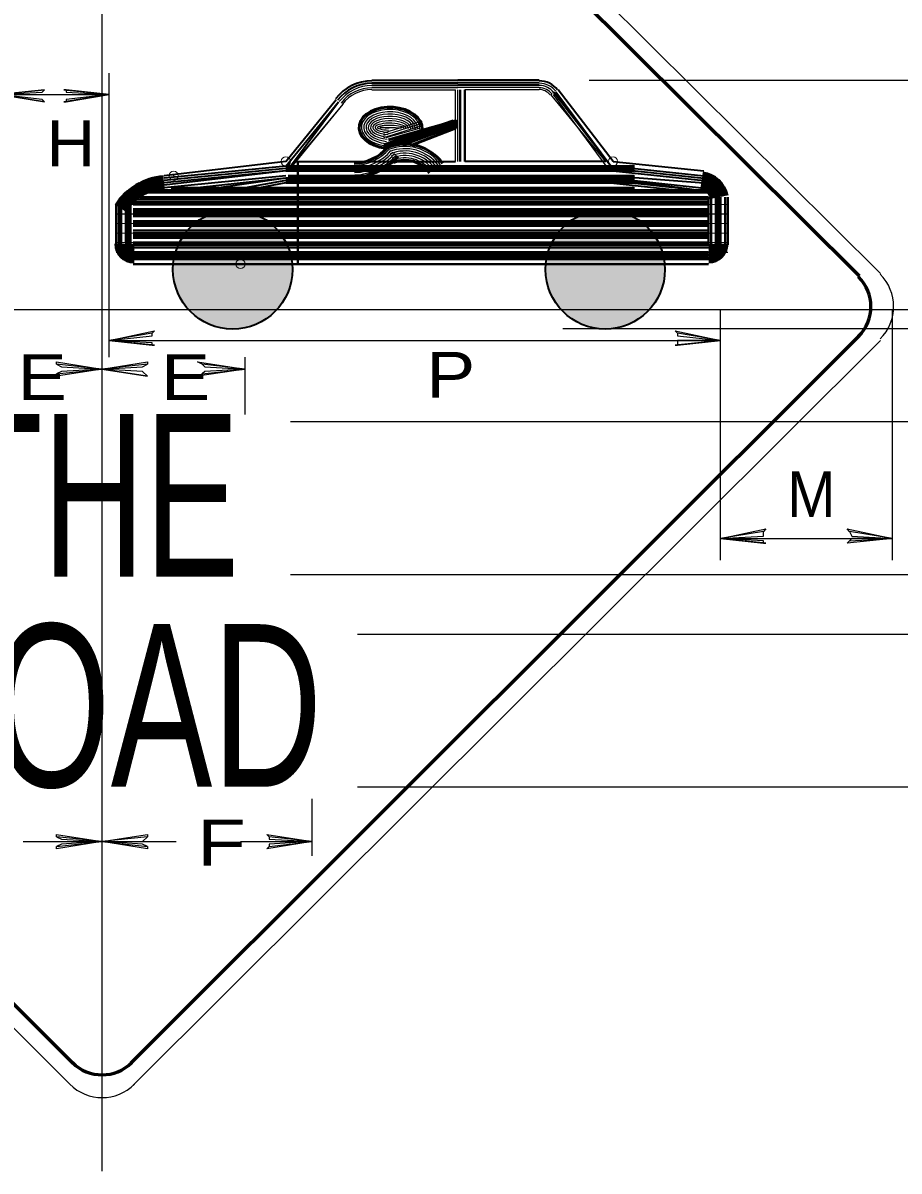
# Model space of a CAD drawing. Extents: x -0.018 to 0.195, y -0.006 to 0.263.
# Drawn here: x 0.0839 to 0.1297, y 0.1052 to 0.1654 of the extents above; entities that cross this region are included whole.
import ezdxf
from ezdxf.enums import TextEntityAlignment as Align

# ---------------------------------------------------------------- set-up
doc = ezdxf.new("R2010")
doc.units = 0
doc.header["$LTSCALE"] = 0.00096
doc.header["$PDMODE"] = 32
doc.header["$PDSIZE"] = 0.00048
doc.linetypes.add('DOT_DASHED', pattern=[7.7, 5, -1.2, 0.3, -1.2])
doc.layers.add('1', color=7, linetype='Continuous', lineweight=25)
doc.layers.add('12', color=7, linetype='Continuous', lineweight=13)

msp = doc.modelspace()

# ---------------------------------------------------------------- hatches: boundary and pattern name
at = {"layer": '12'}
for points in [[(0.097966, 0.152467, 1), (0.091717, 0.152467, 1)], [(0.117463, 0.152467, 1), (0.111214, 0.152467, 1)]]:
    msp.add_hatch(color=256, dxfattribs=at).paths.add_polyline_path(points)

# ---------------------------------------------------------------- linework, layer by layer
at = {"layer": '1', "linetype": 'DOT_DASHED'}
for p, q in [((0.088, 0.20175), (0.088, 0.10525)), ((0.032375, 0.150375), (0.143125, 0.150375))]:
    msp.add_line(p, q, dxfattribs=at)
at = {"layer": '1'}
for p, q in [((0.1135, 0.162375), (0.1335, 0.162375)), ((0.129375, 0.13725), (0.129375, 0.150375)), ((0.112125, 0.149375), (0.154625, 0.149375)), ((0.097875, 0.1445), (0.143, 0.1445)), ((0.120375, 0.138375), (0.129375, 0.138375)), ((0.097875, 0.1365), (0.143, 0.1365)), ((0.101375, 0.133375), (0.143, 0.133375)), ((0.101375, 0.125375), (0.143, 0.125375))]:
    msp.add_line(p, q, dxfattribs=at)
msp.add_lwpolyline([(0.127125, 0.13875), (0.12725, 0.1385), (0.129375, 0.138375), (0.127125, 0.13875), (0.127, 0.138875), (0.129375, 0.138375), (0.12725, 0.138375), (0.127125, 0.13825), (0.129375, 0.138375), (0.127, 0.138125), (0.127125, 0.13825)], dxfattribs=at)
at = {"layer": '12', "lineweight": 25}
for p, q in [((0.089625, 0.191125), (0.12875, 0.15225)), ((0.088375, 0.147875), (0.088375, 0.16275)), ((0.102125, 0.162), (0.106625, 0.162)), ((0.102125, 0.161875), (0.1065, 0.161875)), ((0.1065, 0.158125), (0.1065, 0.161875)), ((0.110875, 0.162), (0.106625, 0.162)), ((0.106625, 0.158125), (0.106625, 0.161875)), ((0.110875, 0.161875), (0.107, 0.161875)), ((0.082625, 0.161625), (0.088375, 0.161625)), ((0.114375, 0.158125), (0.1115, 0.161625)), ((0.1145, 0.15775), (0.111625, 0.161625)), ((0.097875, 0.15775), (0.100625, 0.161125)), ((0.097875, 0.15775), (0.100625, 0.161125)), ((0.098125, 0.158125), (0.100625, 0.161125)), ((0.10275, 0.159625), (0.10475, 0.16025)), ((0.10275, 0.1595), (0.10475, 0.160125)), ((0.10275, 0.159375), (0.10475, 0.16)), ((0.102875, 0.159375), (0.104625, 0.159875)), ((0.08875, 0.155375), (0.12075, 0.155375)), ((0.08875, 0.153375), (0.12075, 0.153375)), ((0.120375, 0.13725), (0.120375, 0.150375)), ((0.086375, 0.10975), (0.04725, 0.14875)), ((0.088375, 0.14875), (0.120375, 0.14875)), ((0.12875, 0.14875), (0.089625, 0.10975)), ((0.0955, 0.144875), (0.0955, 0.147875)), ((0.099, 0.12175), (0.099, 0.12475)), ((0.09525, 0.1225), (0.099, 0.1225))]:
    msp.add_line(p, q, dxfattribs=at)
at = {"layer": '12', "lineweight": 60}
for p, q in [((0.0895, 0.190125), (0.127625, 0.152125)), ((0.0865, 0.110875), (0.048375, 0.149)), ((0.127625, 0.149), (0.0895, 0.110875))]:
    msp.add_line(p, q, dxfattribs=at)
at = {"layer": '12', "lineweight": 35}
for p, q in [((0.102125, 0.162375), (0.106625, 0.162375)), ((0.110875, 0.162375), (0.106625, 0.162375)), ((0.102125, 0.16225), (0.106625, 0.16225)), ((0.102125, 0.162125), (0.106625, 0.162125)), ((0.110875, 0.16225), (0.106625, 0.16225)), ((0.110875, 0.162125), (0.106625, 0.162125)), ((0.114625, 0.157875), (0.111625, 0.16175)), ((0.114625, 0.157875), (0.11175, 0.16175)), ((0.11475, 0.158125), (0.111875, 0.161875)), ((0.097625, 0.158125), (0.10025, 0.161375)), ((0.097625, 0.157875), (0.100375, 0.16125)), ((0.097875, 0.157875), (0.100375, 0.16125)), ((0.097625, 0.158125), (0.09125, 0.157375)), ((0.097625, 0.157875), (0.09125, 0.15725)), ((0.097625, 0.15775), (0.09125, 0.157125)), ((0.097625, 0.157625), (0.09125, 0.157)), ((0.097625, 0.157625), (0.09125, 0.156875)), ((0.098125, 0.158125), (0.1065, 0.158125)), ((0.114375, 0.158125), (0.107, 0.158125)), ((0.11475, 0.158125), (0.1195, 0.157625)), ((0.11475, 0.157875), (0.1195, 0.157375)), ((0.11475, 0.15775), (0.1195, 0.15725)), ((0.11475, 0.157625), (0.1195, 0.157125)), ((0.11475, 0.157625), (0.1195, 0.157125)), ((0.097625, 0.157375), (0.09125, 0.15675)), ((0.097625, 0.15725), (0.093, 0.15675)), ((0.097625, 0.15725), (0.094125, 0.15675)), ((0.097625, 0.157125), (0.0955, 0.15675)), ((0.097625, 0.157), (0.09625, 0.15675)), ((0.114625, 0.15725), (0.11925, 0.156625)), ((0.114625, 0.157125), (0.11925, 0.156625)), ((0.114625, 0.157), (0.11925, 0.1565)), ((0.11475, 0.157375), (0.1195, 0.157)), ((0.11475, 0.15725), (0.119375, 0.15675))]:
    msp.add_line(p, q, dxfattribs=at)
at = {"layer": '12', "lineweight": 40}
for p, q in [((0.10675, 0.158125), (0.10675, 0.161875)), ((0.10675, 0.158125), (0.10675, 0.161875)), ((0.107, 0.158125), (0.107, 0.161875)), ((0.097625, 0.157875), (0.115875, 0.157875)), ((0.097625, 0.15775), (0.115875, 0.15775)), ((0.097625, 0.157625), (0.115875, 0.157625)), ((0.097625, 0.157625), (0.115875, 0.157625)), ((0.09825, 0.15275), (0.09825, 0.158125)), ((0.097625, 0.15725), (0.115875, 0.15725)), ((0.097625, 0.157125), (0.115875, 0.157125)), ((0.097625, 0.157125), (0.115875, 0.157125)), ((0.097625, 0.157), (0.115875, 0.157)), ((0.09775, 0.157375), (0.115875, 0.157375)), ((0.090125, 0.1565), (0.11975, 0.1565)), ((0.0905, 0.156625), (0.11975, 0.156625)), ((0.090875, 0.156625), (0.11975, 0.156625)), ((0.091625, 0.15675), (0.115875, 0.15675)), ((0.08875, 0.15375), (0.08875, 0.155875)), ((0.088875, 0.15375), (0.088875, 0.155875)), ((0.089, 0.15375), (0.089, 0.155875)), ((0.089, 0.15375), (0.089, 0.155875)), ((0.08925, 0.15375), (0.08925, 0.155875)), ((0.089375, 0.15375), (0.089375, 0.155875)), ((0.0895, 0.15375), (0.0895, 0.155875)), ((0.0895, 0.15375), (0.0895, 0.155875)), ((0.089625, 0.156125), (0.11975, 0.156125)), ((0.089625, 0.156125), (0.11975, 0.156125)), ((0.089625, 0.156), (0.11975, 0.156)), ((0.089625, 0.155875), (0.11975, 0.155875)), ((0.09, 0.15625), (0.11975, 0.15625)), ((0.11975, 0.15625), (0.11975, 0.15375)), ((0.119875, 0.15625), (0.119875, 0.15375)), ((0.119875, 0.15625), (0.119875, 0.15375)), ((0.120125, 0.15625), (0.120125, 0.15375)), ((0.12025, 0.15625), (0.12025, 0.15375)), ((0.120375, 0.15625), (0.120375, 0.15375)), ((0.120375, 0.15625), (0.120375, 0.15375)), ((0.120625, 0.15625), (0.120625, 0.15375)), ((0.12075, 0.15625), (0.12075, 0.15375)), ((0.089625, 0.155625), (0.11975, 0.155625)), ((0.089625, 0.155625), (0.11975, 0.155625)), ((0.089625, 0.1555), (0.11975, 0.1555)), ((0.089625, 0.155375), (0.11975, 0.155375)), ((0.089625, 0.15525), (0.11975, 0.15525)), ((0.089625, 0.15525), (0.11975, 0.15525)), ((0.089625, 0.155), (0.11975, 0.155)), ((0.089625, 0.154875), (0.11975, 0.154875)), ((0.089625, 0.15475), (0.11975, 0.15475)), ((0.089625, 0.15475), (0.11975, 0.15475)), ((0.089625, 0.1545), (0.11975, 0.1545)), ((0.089625, 0.154375), (0.11975, 0.154375)), ((0.089625, 0.15425), (0.11975, 0.15425)), ((0.089625, 0.15425), (0.11975, 0.15425)), ((0.089625, 0.154125), (0.11975, 0.154125)), ((0.089625, 0.153875), (0.11975, 0.153875)), ((0.089625, 0.15375), (0.11975, 0.15375)), ((0.089625, 0.15375), (0.11975, 0.15375)), ((0.089625, 0.153625), (0.11975, 0.153625)), ((0.089625, 0.153375), (0.11975, 0.153375)), ((0.089625, 0.15325), (0.11975, 0.15325)), ((0.089625, 0.15325), (0.11975, 0.15325)), ((0.089625, 0.153125), (0.11975, 0.153125)), ((0.089625, 0.153), (0.11975, 0.153)), ((0.089625, 0.15275), (0.11975, 0.15275))]:
    msp.add_line(p, q, dxfattribs=at)
at = {"layer": '12', "lineweight": 53}
for p, q in [((0.106625, 0.16025), (0.10275, 0.158875)), ((0.106375, 0.16025), (0.10275, 0.159)), ((0.1065, 0.160125), (0.1035, 0.159)), ((0.1065, 0.16), (0.10375, 0.159))]:
    msp.add_line(p, q, dxfattribs=at)
at = {"layer": '12'}
for p, q in [((0.08875, 0.155875), (0.12075, 0.155875)), ((0.08875, 0.154875), (0.12075, 0.154875)), ((0.08875, 0.154375), (0.12075, 0.154375)), ((0.08875, 0.153875), (0.12075, 0.153875)), ((0.089875, 0.15275), (0.1195, 0.15275))]:
    msp.add_line(p, q, dxfattribs=at)
at = {"layer": '12', "lineweight": 25}
for points in [[(0.085, 0.16125), (0.084875, 0.161375), (0.082625, 0.161625), (0.085, 0.16125), (0.085, 0.16125), (0.082625, 0.161625), (0.084875, 0.16175), (0.085, 0.161875), (0.082625, 0.161625), (0.085, 0.161875), (0.085, 0.161875)], [(0.086125, 0.161875), (0.086125, 0.16175), (0.088375, 0.161625), (0.086125, 0.161875), (0.086, 0.161875), (0.088375, 0.161625), (0.086125, 0.161375), (0.086125, 0.16125), (0.088375, 0.161625), (0.086, 0.16125), (0.086125, 0.16125)], [(0.090625, 0.1485), (0.090625, 0.148625), (0.088375, 0.14875), (0.090625, 0.1485), (0.09075, 0.1485), (0.088375, 0.14875), (0.090625, 0.149), (0.090625, 0.149125), (0.088375, 0.14875), (0.09075, 0.14925), (0.090625, 0.149125)], [(0.118125, 0.149125), (0.118125, 0.149), (0.120375, 0.14875), (0.118125, 0.149125), (0.118, 0.14925), (0.120375, 0.14875), (0.118125, 0.14875), (0.118125, 0.1485), (0.120375, 0.14875), (0.118, 0.1485), (0.118125, 0.1485)], [(0.085625, 0.1475), (0.085875, 0.147375), (0.088, 0.14725), (0.085625, 0.1475), (0.085625, 0.147625), (0.088, 0.14725), (0.085875, 0.147125), (0.085625, 0.147), (0.088, 0.14725), (0.085625, 0.146875), (0.085625, 0.147)], [(0.090375, 0.146875), (0.090125, 0.147125), (0.088, 0.14725), (0.090375, 0.146875), (0.090375, 0.146875), (0.088, 0.14725), (0.090125, 0.147375), (0.090375, 0.1475), (0.088, 0.14725), (0.090375, 0.147625), (0.090375, 0.1475)], [(0.09325, 0.1475), (0.093375, 0.147375), (0.0955, 0.14725), (0.09325, 0.1475), (0.093, 0.147625), (0.0955, 0.14725), (0.093375, 0.147125), (0.09325, 0.147), (0.0955, 0.14725), (0.093, 0.146875), (0.09325, 0.147)], [(0.122625, 0.138125), (0.122625, 0.13825), (0.120375, 0.138375), (0.122625, 0.138125), (0.12275, 0.138125), (0.120375, 0.138375), (0.122625, 0.1385), (0.122625, 0.13875), (0.120375, 0.138375), (0.12275, 0.138875), (0.122625, 0.13875)], [(0.085625, 0.12275), (0.085875, 0.122625), (0.088, 0.1225), (0.085625, 0.12275), (0.085625, 0.122875), (0.088, 0.1225), (0.085875, 0.122375), (0.085625, 0.12225), (0.088, 0.1225), (0.085625, 0.122125), (0.085625, 0.12225)], [(0.090375, 0.12225), (0.090125, 0.122375), (0.088, 0.1225), (0.090375, 0.12225), (0.090375, 0.122125), (0.088, 0.1225), (0.090125, 0.1225), (0.090375, 0.12275), (0.088, 0.1225), (0.090375, 0.122875), (0.090375, 0.12275)], [(0.09675, 0.12275), (0.09675, 0.122625), (0.099, 0.1225), (0.09675, 0.12275), (0.096625, 0.122875), (0.099, 0.1225), (0.09675, 0.122375), (0.09675, 0.12225), (0.099, 0.1225), (0.096625, 0.122125), (0.09675, 0.12225)], [(0.083875, 0.1225), (0.088, 0.1225), (0.091875, 0.1225)]]:
    msp.add_lwpolyline(points, dxfattribs=at)
at = {"layer": '12', "lineweight": 53}
msp.add_lwpolyline([(0.103, 0.15925), (0.1065, 0.16025), (0.1065, 0.159875), (0.10425, 0.159)], dxfattribs=at)
at = {"layer": '12', "lineweight": 35}
for centre in [(0.094842, 0.152467), (0.114339, 0.152467)]:
    msp.add_circle(centre, 0.003125, dxfattribs=at)
for centre, radius, start, end in [((0.102131, 0.159941), 0.0024, 90, 142.46745), ((0.102131, 0.159941), 0.00228, 90, 142.46745), ((0.11089, 0.161141), 0.0012, 37.53138, 90)]:
    msp.add_arc(centre, radius, start, end, dxfattribs=at)
at = {"layer": '12', "lineweight": 25}
for centre, radius, start, end in [((0.102131, 0.159941), 0.00216, 90, 142.46745), ((0.102131, 0.159941), 0.00204, 90, 142.46745), ((0.102131, 0.159941), 0.00195, 90, 142.46745), ((0.110876, 0.161163), 0.000728, 37.53138, 90), ((0.11089, 0.161141), 0.00108, 37.53138, 90), ((0.11089, 0.161141), 0.00096, 37.53138, 90), ((0.11089, 0.161141), 0.00084, 37.53138, 90), ((0.101108, 0.160461), 0.002563, 272.29644, 318.79272), ((0.103861, 0.156626), 0.002287, 35.41012, 112.33951), ((0.103861, 0.156626), 0.002167, 35.41012, 112.33951), ((0.101108, 0.160461), 0.002683, 272.29644, 318.79272), ((0.101108, 0.160461), 0.002803, 272.29644, 318.79272), ((0.101108, 0.160461), 0.002923, 272.29644, 318.79272), ((0.101108, 0.160461), 0.003043, 272.29644, 318.79272), ((0.103861, 0.156626), 0.002047, 35.41012, 112.33951), ((0.103861, 0.156626), 0.001927, 35.41012, 112.33951), ((0.103861, 0.156626), 0.001807, 35.41012, 112.33951), ((0.103861, 0.156626), 0.001687, 35.41012, 112.33951), ((0.127031, 0.150523), 0.0024, 315, 45), ((0.088007, 0.111498), 0.0024, 225, 315)]:
    msp.add_arc(centre, radius, start, end, dxfattribs=at)
at = {"layer": '12', "lineweight": 53}
for centre, radius, start, end in [((0.101108, 0.160461), 0.002443, 272.29644, 318.79272), ((0.103861, 0.156626), 0.002407, 35.41012, 112.33951), ((0.101108, 0.160461), 0.003163, 272.29644, 318.79272), ((0.103861, 0.156626), 0.001567, 35.41012, 112.33951), ((0.091505, 0.154029), 0.003325, 94.96224, 146.96527), ((0.091505, 0.154029), 0.003205, 94.96224, 146.96527), ((0.091505, 0.154029), 0.003085, 94.96224, 146.96527), ((0.091505, 0.154029), 0.002965, 94.96224, 146.96527), ((0.119242, 0.156041), 0.000902, 11.54691, 82.31176), ((0.119242, 0.156041), 0.001022, 11.54691, 82.31176), ((0.119242, 0.156041), 0.001142, 11.54691, 82.31176), ((0.119242, 0.156041), 0.001262, 11.54691, 82.31176), ((0.119242, 0.156041), 0.001382, 11.54691, 82.31176), ((0.119242, 0.156041), 0.001502, 11.54691, 82.31176), ((0.091505, 0.154029), 0.002845, 94.96224, 146.96527), ((0.091505, 0.154029), 0.002725, 94.96224, 146.96527), ((0.119242, 0.156041), 0.000662, 11.54691, 82.31176), ((0.119242, 0.156041), 0.000782, 11.54691, 82.31176), ((0.089677, 0.153802), 0.00096, 180, 270), ((0.089677, 0.153802), 0.00084, 180, 270), ((0.089677, 0.153802), 0.00072, 180, 270), ((0.089677, 0.153802), 0.0006, 180, 270), ((0.089677, 0.153802), 0.00048, 180, 270), ((0.089677, 0.153802), 0.00036, 180, 270), ((0.089677, 0.153802), 0.00024, 180, 270), ((0.089677, 0.153802), 0.00012, 180, 270), ((0.119753, 0.153802), 0.00096, 270, 0), ((0.119753, 0.153802), 0.00084, 270, 0), ((0.119753, 0.153802), 0.00072, 270, 0), ((0.119753, 0.153802), 0.0006, 270, 0), ((0.119753, 0.153802), 0.00048, 270, 0), ((0.119753, 0.153802), 0.00036, 270, 0), ((0.119753, 0.153802), 0.00024, 270, 0), ((0.119753, 0.153802), 0.00012, 270, 0)]:
    msp.add_arc(centre, radius, start, end, dxfattribs=at)
at = {"layer": '12', "lineweight": 60}
for centre, start, end in [((0.126042, 0.150523), 315, 45), ((0.088007, 0.112488), 225, 315)]:
    msp.add_arc(centre, 0.0022, start, end, dxfattribs=at)
at = {"layer": '12', "lineweight": 53}
for major_axis, ratio, start_param, end_param in [((-0.00165, 0.000049), 0.656276, 3.120994, 7.708521), ((-0.001291, 0.000038), 0.56044, 2.348331, 2.578157)]:
    msp.add_ellipse((0.103108, 0.159884), major_axis=major_axis, ratio=ratio, start_param=start_param, end_param=end_param, dxfattribs=at)
at = {"layer": '12', "lineweight": 25}
for major_axis, ratio in [((-0.00153, 0.000045), 0.629337), ((-0.00141, 0.000042), 0.597818), ((-0.001291, 0.000038), 0.56044), ((-0.001171, 0.000035), 0.515402), ((-0.001051, 0.000031), 0.460081), ((-0.000931, 0.000028), 0.390502), ((-0.000811, 0.000024), 0.300337), ((-0.000691, 0.00002), 0.178863), ((-0.000571, 0.000017), 0.006348)]:
    msp.add_ellipse((0.103108, 0.159884), major_axis=major_axis, ratio=ratio, start_param=3.120994, end_param=7.708521, dxfattribs=at)
at = {"layer": '12'}
for p in [(0.097625, 0.158125), (0.11475, 0.158125), (0.09175, 0.157375), (0.09525, 0.15275)]:
    msp.add_point(p, dxfattribs=at)

# ---------------------------------------------------------------- texts
at = {"layer": '1', "width": 0.95}
msp.add_text('M', height=0.002399, dxfattribs=at).set_placement((0.125125, 0.1395), align=Align.CENTER)
at = {"layer": '12'}
for s, width, p in [('H', 1.1, (0.086375, 0.157875)), ('E', 1.2, (0.084875, 0.145625)), ('E', 1.2, (0.092375, 0.145625)), ('P', 1.2, (0.10625, 0.14575)), ('F', 1.3, (0.09425, 0.12125))]:
    msp.add_text(s, height=0.002399, dxfattribs=dict(at, width=width)).set_placement(p, align=Align.CENTER)
for s, width, p in [('THE', 0.65, (0.080375, 0.136375)), ('ROAD', 0.7, (0.0765, 0.125375))]:
    msp.add_text(s, height=0.008517, dxfattribs=dict(at, width=width)).set_placement(p)

doc.saveas('drawing.dxf')
